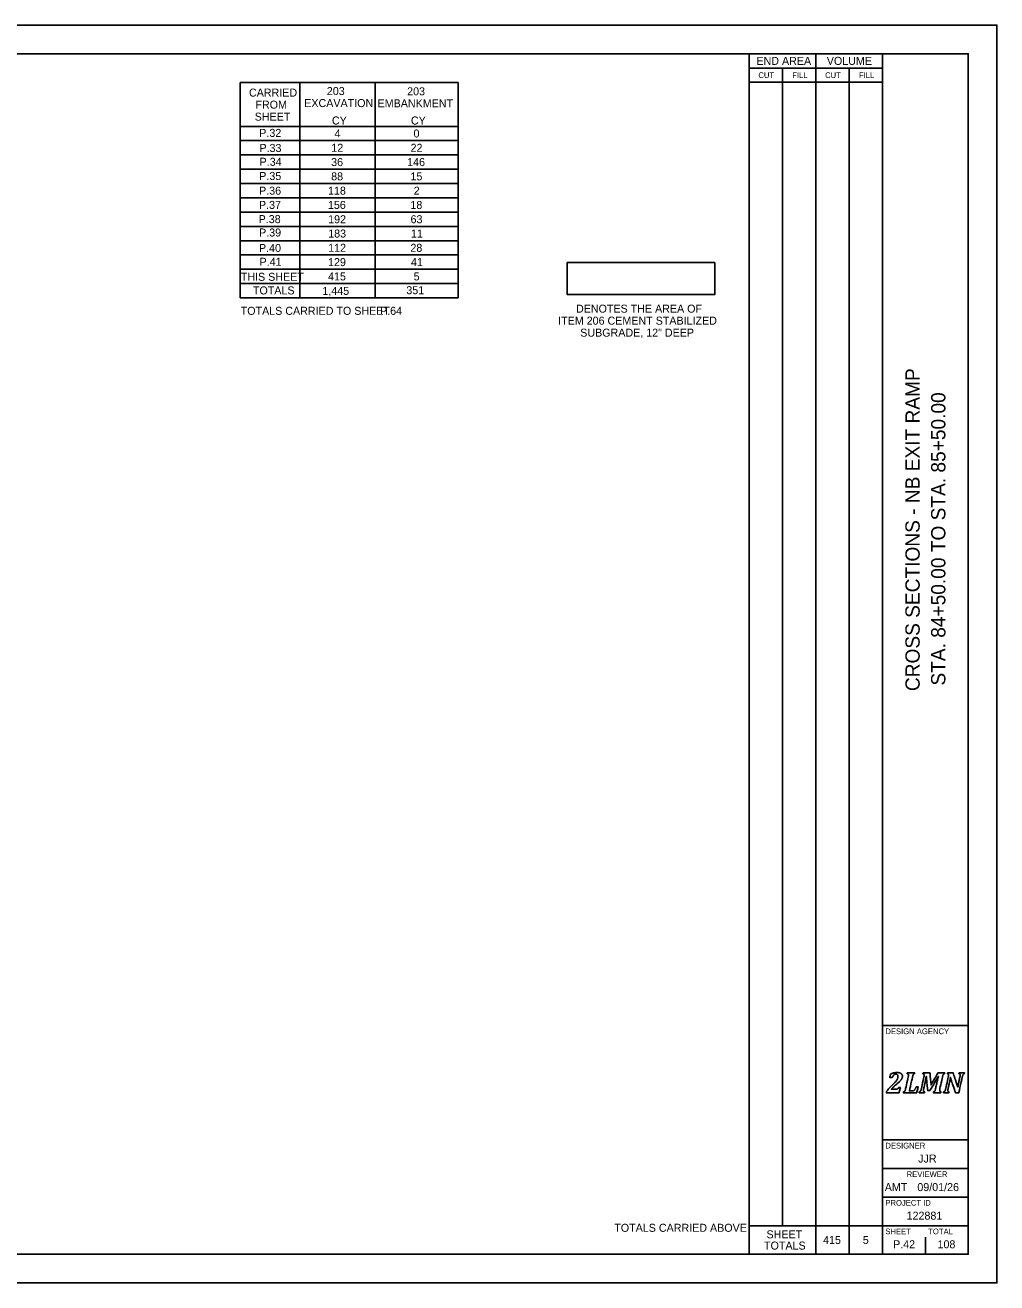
# Model space of a CAD drawing. Extents: x -32 to 34, y 0 to 22.
# Drawn here: x 17 to 34, y 0 to 22 of the extents above; entities that cross this region are included whole.
import ezdxf

# ---------------------------------------------------------------- set-up
doc = ezdxf.new("R2010")
doc.units = 0
for name, color, linetype in [('MD_P_Surface_Chemically_Stabilized_Subgrade', 7, 'Continuous'), ('SH_Border', 7, 'Continuous'), ('SH_Cut_Line', 7, 'Continuous'), ('SH_Data', 7, 'Continuous'), ('SH_Text', 7, 'Continuous')]:
    doc.layers.add(name, color=color, linetype=linetype)

msp = doc.modelspace()

# ---------------------------------------------------------------- linework, layer by layer
at = {"layer": 'MD_P_Surface_Chemically_Stabilized_Subgrade'}
for p, q in [((26.484, 17.846), (26.484, 17.287)), ((26.484, 17.846), (29.065, 17.846)), ((29.065, 17.287), (29.065, 17.846)), ((26.484, 17.287), (29.065, 17.287))]:
    msp.add_line(p, q, dxfattribs=at)
msp.add_lwpolyline([(29.065, 17.846), (29.065, 17.287), (26.484, 17.287), (26.484, 17.846)], close=True, dxfattribs=at)
at = {"layer": 'SH_Border'}
for p, q in [((32, 0.5), (32, 21.5)), ((32, 4.5), (33.5, 4.5)), ((32, 2.5), (33.5, 2.5)), ((32, 2), (33.5, 2)), ((32, 1.5), (33.5, 1.5)), ((32, 1), (33.5, 1))]:
    msp.add_line(p, q, dxfattribs=at)
msp.add_lwpolyline([(1.5, 21.5), (33.5, 21.5), (33.5, 0.5), (1.5, 0.5)], close=True, dxfattribs=at)
at = {"layer": 'SH_Cut_Line'}
msp.add_lwpolyline([(0, 0), (34, 0), (34, 22), (0, 22)], close=True, dxfattribs=at)
at = {"layer": 'SH_Data'}
for p, q in [((29.666, 0.5), (29.666, 21.5)), ((30.833, 0.5), (30.833, 21.5)), ((29.666, 21.25), (32, 21.25)), ((30.25, 1), (30.25, 21.25)), ((31.417, 0.5), (31.417, 21.25)), ((29.666, 21), (32, 21)), ((32.75, 3.5), (32.75, 3.5)), ((29.666, 1), (32, 1)), ((29.958, 0.75), (29.958, 0.75)), ((30.542, 0.75), (30.542, 0.75)), ((31.125, 0.75), (31.125, 0.75)), ((31.708, 0.75), (31.708, 0.75)), ((32.375, 0.675), (32.375, 0.675)), ((32.75, 0.5), (32.75, 0.8))]:
    msp.add_line(p, q, dxfattribs=at)
for points in [[(32.237, 3.388), (32.246, 3.388), (32.253, 3.389), (32.258, 3.39), (32.263, 3.392), (32.267, 3.394), (32.27, 3.397), (32.273, 3.401), (32.277, 3.408), (32.281, 3.417), (32.281, 3.417), (32.312, 3.417), (32.312, 3.417), (32.312, 3.417), (32.29, 3.326), (32.29, 3.326), (32.29, 3.326), (32.066, 3.326), (32.066, 3.326), (32.066, 3.326), (32.069, 3.343), (32.069, 3.343), (32.078, 3.358), (32.091, 3.375), (32.106, 3.394), (32.122, 3.412), (32.144, 3.435), (32.172, 3.462), (32.197, 3.486), (32.217, 3.506), (32.23, 3.521), (32.243, 3.537), (32.253, 3.551), (32.259, 3.566), (32.266, 3.58), (32.269, 3.595), (32.269, 3.61), (32.269, 3.622), (32.266, 3.632), (32.26, 3.64), (32.253, 3.647), (32.245, 3.65), (32.234, 3.65), (32.22, 3.65), (32.208, 3.646), (32.198, 3.636), (32.188, 3.627), (32.18, 3.613), (32.172, 3.593), (32.172, 3.593), (32.126, 3.593), (32.126, 3.593), (32.126, 3.593), (32.14, 3.654), (32.14, 3.654), (32.166, 3.663), (32.188, 3.669), (32.205, 3.673), (32.223, 3.676), (32.24, 3.678), (32.258, 3.678), (32.278, 3.678), (32.295, 3.675), (32.309, 3.669), (32.322, 3.664), (32.332, 3.656), (32.339, 3.646), (32.345, 3.637), (32.348, 3.626), (32.348, 3.613), (32.348, 3.602), (32.346, 3.591), (32.342, 3.581), (32.339, 3.571), (32.333, 3.56), (32.324, 3.549), (32.315, 3.539), (32.304, 3.526), (32.289, 3.513), (32.275, 3.499), (32.254, 3.482), (32.228, 3.46), (32.216, 3.45), (32.202, 3.438), (32.188, 3.425), (32.174, 3.412), (32.162, 3.4), (32.154, 3.391), (32.154, 3.391), (32.153, 3.388), (32.153, 3.388), (32.153, 3.388), (32.237, 3.388), (32.237, 3.388)], [(32.237, 3.388), (32.237, 3.388), (32.153, 3.388), (32.153, 3.388), (32.153, 3.388), (32.154, 3.391), (32.154, 3.391), (32.162, 3.4), (32.174, 3.412), (32.188, 3.425), (32.202, 3.438), (32.216, 3.45), (32.228, 3.46), (32.254, 3.482), (32.275, 3.499), (32.289, 3.513), (32.304, 3.526), (32.315, 3.539), (32.324, 3.549), (32.333, 3.56), (32.339, 3.571), (32.342, 3.581), (32.346, 3.591), (32.348, 3.602), (32.348, 3.613), (32.348, 3.626), (32.345, 3.637), (32.339, 3.646), (32.332, 3.656), (32.322, 3.664), (32.309, 3.669), (32.295, 3.675), (32.278, 3.678), (32.258, 3.678), (32.24, 3.678), (32.223, 3.676), (32.205, 3.673), (32.188, 3.669), (32.166, 3.663), (32.14, 3.654), (32.14, 3.654), (32.126, 3.593), (32.126, 3.593), (32.126, 3.593), (32.172, 3.593), (32.172, 3.593), (32.18, 3.613), (32.188, 3.627), (32.198, 3.636), (32.208, 3.646), (32.22, 3.65), (32.234, 3.65), (32.245, 3.65), (32.253, 3.647), (32.26, 3.64), (32.266, 3.632), (32.269, 3.622), (32.269, 3.61), (32.269, 3.595), (32.266, 3.58), (32.259, 3.566), (32.253, 3.551), (32.243, 3.537), (32.23, 3.521), (32.217, 3.506), (32.197, 3.486), (32.172, 3.462), (32.144, 3.435), (32.122, 3.412), (32.106, 3.394), (32.091, 3.375), (32.078, 3.358), (32.069, 3.343), (32.069, 3.343), (32.066, 3.326), (32.066, 3.326), (32.066, 3.326), (32.29, 3.326), (32.29, 3.326), (32.29, 3.326), (32.312, 3.417), (32.312, 3.417), (32.312, 3.417), (32.281, 3.417), (32.281, 3.417), (32.277, 3.408), (32.273, 3.401), (32.27, 3.397), (32.267, 3.394), (32.263, 3.392), (32.258, 3.39), (32.253, 3.389), (32.246, 3.388), (32.237, 3.388)], [(32.518, 3.356), (32.527, 3.356), (32.533, 3.357), (32.538, 3.358), (32.542, 3.36), (32.546, 3.362), (32.55, 3.365), (32.554, 3.368), (32.558, 3.372), (32.562, 3.377), (32.567, 3.382), (32.571, 3.388), (32.576, 3.397), (32.58, 3.405), (32.585, 3.415), (32.589, 3.427), (32.589, 3.427), (32.624, 3.427), (32.624, 3.427), (32.624, 3.427), (32.598, 3.326), (32.598, 3.326), (32.598, 3.326), (32.365, 3.326), (32.365, 3.326), (32.365, 3.326), (32.369, 3.343), (32.369, 3.343), (32.376, 3.345), (32.381, 3.348), (32.385, 3.351), (32.389, 3.355), (32.392, 3.36), (32.395, 3.366), (32.398, 3.373), (32.4, 3.382), (32.403, 3.395), (32.403, 3.395), (32.449, 3.605), (32.449, 3.605), (32.452, 3.615), (32.453, 3.625), (32.453, 3.635), (32.453, 3.642), (32.451, 3.647), (32.448, 3.651), (32.444, 3.654), (32.439, 3.656), (32.432, 3.657), (32.432, 3.657), (32.435, 3.674), (32.435, 3.674), (32.435, 3.674), (32.563, 3.674), (32.563, 3.674), (32.563, 3.674), (32.559, 3.657), (32.559, 3.657), (32.552, 3.655), (32.547, 3.652), (32.543, 3.649), (32.539, 3.645), (32.536, 3.64), (32.533, 3.634), (32.531, 3.627), (32.528, 3.618), (32.525, 3.605), (32.525, 3.605), (32.47, 3.356), (32.47, 3.356), (32.47, 3.356), (32.518, 3.356), (32.518, 3.356)], [(32.518, 3.356), (32.518, 3.356), (32.47, 3.356), (32.47, 3.356), (32.47, 3.356), (32.525, 3.605), (32.525, 3.605), (32.528, 3.618), (32.531, 3.627), (32.533, 3.634), (32.536, 3.64), (32.539, 3.645), (32.543, 3.649), (32.547, 3.652), (32.552, 3.655), (32.559, 3.657), (32.559, 3.657), (32.563, 3.674), (32.563, 3.674), (32.563, 3.674), (32.435, 3.674), (32.435, 3.674), (32.435, 3.674), (32.432, 3.657), (32.432, 3.657), (32.439, 3.656), (32.444, 3.654), (32.448, 3.651), (32.451, 3.647), (32.453, 3.642), (32.453, 3.635), (32.453, 3.625), (32.452, 3.615), (32.449, 3.605), (32.449, 3.605), (32.403, 3.395), (32.403, 3.395), (32.4, 3.382), (32.398, 3.373), (32.395, 3.366), (32.392, 3.36), (32.389, 3.355), (32.385, 3.351), (32.381, 3.348), (32.376, 3.345), (32.369, 3.343), (32.369, 3.343), (32.365, 3.326), (32.365, 3.326), (32.365, 3.326), (32.598, 3.326), (32.598, 3.326), (32.598, 3.326), (32.624, 3.427), (32.624, 3.427), (32.624, 3.427), (32.589, 3.427), (32.589, 3.427), (32.585, 3.415), (32.58, 3.405), (32.576, 3.397), (32.571, 3.388), (32.567, 3.382), (32.562, 3.377), (32.558, 3.372), (32.554, 3.368), (32.55, 3.365), (32.546, 3.362), (32.542, 3.36), (32.538, 3.358), (32.533, 3.357), (32.527, 3.356), (32.518, 3.356)], [(32.829, 3.674), (32.829, 3.674), (32.849, 3.461), (32.849, 3.461), (32.849, 3.461), (32.969, 3.674), (32.969, 3.674), (32.969, 3.674), (33.087, 3.674), (33.087, 3.674), (33.087, 3.674), (33.084, 3.657), (33.084, 3.657), (33.077, 3.655), (33.071, 3.652), (33.067, 3.649), (33.064, 3.645), (33.06, 3.64), (33.058, 3.634), (33.055, 3.627), (33.052, 3.618), (33.05, 3.605), (33.05, 3.605), (33.003, 3.395), (33.003, 3.395), (33.002, 3.39), (33.002, 3.387), (33.001, 3.384), (33.001, 3.382), (33.001, 3.379), (33, 3.376), (33, 3.373), (33, 3.369), (33, 3.365), (33, 3.358), (33.002, 3.353), (33.005, 3.349), (33.008, 3.346), (33.014, 3.344), (33.021, 3.343), (33.021, 3.343), (33.018, 3.326), (33.018, 3.326), (33.018, 3.326), (32.89, 3.326), (32.89, 3.326), (32.89, 3.326), (32.893, 3.343), (32.893, 3.343), (32.9, 3.345), (32.906, 3.348), (32.91, 3.351), (32.914, 3.355), (32.917, 3.36), (32.919, 3.366), (32.922, 3.373), (32.925, 3.382), (32.928, 3.395), (32.928, 3.395), (32.951, 3.502), (32.951, 3.502), (32.954, 3.513), (32.957, 3.529), (32.962, 3.548), (32.967, 3.568), (32.972, 3.588), (32.978, 3.609), (32.978, 3.609), (32.973, 3.609), (32.973, 3.609), (32.965, 3.594), (32.957, 3.579), (32.948, 3.563), (32.948, 3.563), (32.833, 3.364), (32.833, 3.364), (32.833, 3.364), (32.792, 3.364), (32.792, 3.364), (32.792, 3.364), (32.775, 3.518), (32.775, 3.518), (32.773, 3.537), (32.772, 3.554), (32.77, 3.569), (32.769, 3.583), (32.768, 3.597), (32.768, 3.611), (32.768, 3.611), (32.764, 3.611), (32.764, 3.611), (32.761, 3.596), (32.758, 3.578), (32.755, 3.558), (32.751, 3.538), (32.747, 3.521), (32.744, 3.507), (32.744, 3.507), (32.72, 3.395), (32.72, 3.395), (32.719, 3.39), (32.718, 3.387), (32.718, 3.384), (32.717, 3.382), (32.717, 3.379), (32.717, 3.376), (32.717, 3.373), (32.716, 3.369), (32.716, 3.365), (32.716, 3.358), (32.718, 3.353), (32.721, 3.349), (32.725, 3.346), (32.73, 3.344), (32.738, 3.343), (32.738, 3.343), (32.734, 3.326), (32.734, 3.326), (32.734, 3.326), (32.641, 3.326), (32.641, 3.326), (32.641, 3.326), (32.644, 3.343), (32.644, 3.343), (32.651, 3.345), (32.657, 3.348), (32.661, 3.351), (32.665, 3.355), (32.668, 3.36), (32.67, 3.366), (32.673, 3.373), (32.676, 3.382), (32.679, 3.395), (32.679, 3.395), (32.725, 3.605), (32.725, 3.605), (32.727, 3.615), (32.728, 3.625), (32.728, 3.635), (32.728, 3.642), (32.727, 3.647), (32.723, 3.651), (32.72, 3.654), (32.715, 3.656), (32.707, 3.657), (32.707, 3.657), (32.711, 3.674), (32.711, 3.674), (32.711, 3.674), (32.829, 3.674), (32.829, 3.674)], [(32.829, 3.674), (32.829, 3.674), (32.711, 3.674), (32.711, 3.674), (32.711, 3.674), (32.707, 3.657), (32.707, 3.657), (32.715, 3.656), (32.72, 3.654), (32.723, 3.651), (32.727, 3.647), (32.728, 3.642), (32.728, 3.635), (32.728, 3.625), (32.727, 3.615), (32.725, 3.605), (32.725, 3.605), (32.679, 3.395), (32.679, 3.395), (32.676, 3.382), (32.673, 3.373), (32.67, 3.366), (32.668, 3.36), (32.665, 3.355), (32.661, 3.351), (32.657, 3.348), (32.651, 3.345), (32.644, 3.343), (32.644, 3.343), (32.641, 3.326), (32.641, 3.326), (32.641, 3.326), (32.734, 3.326), (32.734, 3.326), (32.734, 3.326), (32.738, 3.343), (32.738, 3.343), (32.73, 3.344), (32.725, 3.346), (32.721, 3.349), (32.718, 3.353), (32.716, 3.358), (32.716, 3.365), (32.716, 3.369), (32.717, 3.373), (32.717, 3.376), (32.717, 3.379), (32.717, 3.382), (32.718, 3.384), (32.718, 3.387), (32.719, 3.39), (32.72, 3.395), (32.72, 3.395), (32.744, 3.507), (32.744, 3.507), (32.747, 3.521), (32.751, 3.538), (32.755, 3.558), (32.758, 3.578), (32.761, 3.596), (32.764, 3.611), (32.764, 3.611), (32.768, 3.611), (32.768, 3.611), (32.768, 3.597), (32.769, 3.583), (32.77, 3.569), (32.772, 3.554), (32.773, 3.537), (32.775, 3.518), (32.775, 3.518), (32.792, 3.364), (32.792, 3.364), (32.792, 3.364), (32.833, 3.364), (32.833, 3.364), (32.833, 3.364), (32.948, 3.563), (32.948, 3.563), (32.957, 3.579), (32.965, 3.594), (32.973, 3.609), (32.973, 3.609), (32.978, 3.609), (32.978, 3.609), (32.972, 3.588), (32.967, 3.568), (32.962, 3.548), (32.957, 3.529), (32.954, 3.513), (32.951, 3.502), (32.951, 3.502), (32.928, 3.395), (32.928, 3.395), (32.925, 3.382), (32.922, 3.373), (32.919, 3.366), (32.917, 3.36), (32.914, 3.355), (32.91, 3.351), (32.906, 3.348), (32.9, 3.345), (32.893, 3.343), (32.893, 3.343), (32.89, 3.326), (32.89, 3.326), (32.89, 3.326), (33.018, 3.326), (33.018, 3.326), (33.018, 3.326), (33.021, 3.343), (33.021, 3.343), (33.014, 3.344), (33.008, 3.346), (33.005, 3.349), (33.002, 3.353), (33, 3.358), (33, 3.365), (33, 3.369), (33, 3.373), (33, 3.376), (33.001, 3.379), (33.001, 3.382), (33.001, 3.384), (33.002, 3.387), (33.002, 3.39), (33.003, 3.395), (33.003, 3.395), (33.05, 3.605), (33.05, 3.605), (33.052, 3.618), (33.055, 3.627), (33.058, 3.634), (33.06, 3.64), (33.064, 3.645), (33.067, 3.649), (33.071, 3.652), (33.077, 3.655), (33.084, 3.657), (33.084, 3.657), (33.087, 3.674), (33.087, 3.674), (33.087, 3.674), (32.969, 3.674), (32.969, 3.674), (32.969, 3.674), (32.849, 3.461), (32.849, 3.461), (32.849, 3.461), (32.829, 3.674), (32.829, 3.674)], [(33.137, 3.674), (33.137, 3.674), (33.234, 3.674), (33.234, 3.674), (33.234, 3.674), (33.283, 3.53), (33.283, 3.53), (33.296, 3.49), (33.307, 3.456), (33.315, 3.426), (33.315, 3.426), (33.318, 3.426), (33.318, 3.426), (33.323, 3.455), (33.329, 3.488), (33.337, 3.523), (33.337, 3.523), (33.355, 3.605), (33.355, 3.605), (33.357, 3.615), (33.358, 3.625), (33.358, 3.635), (33.358, 3.642), (33.357, 3.647), (33.353, 3.651), (33.35, 3.654), (33.345, 3.656), (33.337, 3.657), (33.337, 3.657), (33.341, 3.674), (33.341, 3.674), (33.341, 3.674), (33.434, 3.674), (33.434, 3.674), (33.434, 3.674), (33.431, 3.657), (33.431, 3.657), (33.424, 3.655), (33.418, 3.652), (33.414, 3.649), (33.41, 3.645), (33.407, 3.64), (33.405, 3.634), (33.402, 3.627), (33.399, 3.618), (33.396, 3.605), (33.396, 3.605), (33.335, 3.326), (33.335, 3.326), (33.335, 3.326), (33.277, 3.326), (33.277, 3.326), (33.277, 3.326), (33.216, 3.504), (33.216, 3.504), (33.211, 3.518), (33.207, 3.531), (33.204, 3.543), (33.2, 3.556), (33.195, 3.571), (33.19, 3.59), (33.19, 3.59), (33.186, 3.59), (33.186, 3.59), (33.185, 3.579), (33.182, 3.563), (33.179, 3.543), (33.175, 3.523), (33.17, 3.501), (33.165, 3.478), (33.165, 3.478), (33.147, 3.395), (33.147, 3.395), (33.146, 3.39), (33.145, 3.387), (33.145, 3.384), (33.144, 3.382), (33.144, 3.379), (33.144, 3.376), (33.143, 3.373), (33.143, 3.369), (33.143, 3.365), (33.143, 3.358), (33.145, 3.353), (33.148, 3.349), (33.152, 3.346), (33.157, 3.344), (33.164, 3.343), (33.164, 3.343), (33.161, 3.326), (33.161, 3.326), (33.161, 3.326), (33.067, 3.326), (33.067, 3.326), (33.067, 3.326), (33.071, 3.343), (33.071, 3.343), (33.078, 3.345), (33.083, 3.348), (33.087, 3.351), (33.091, 3.355), (33.094, 3.36), (33.097, 3.366), (33.1, 3.373), (33.102, 3.382), (33.105, 3.395), (33.105, 3.395), (33.151, 3.605), (33.151, 3.605), (33.154, 3.615), (33.155, 3.625), (33.155, 3.635), (33.155, 3.642), (33.153, 3.647), (33.15, 3.651), (33.146, 3.654), (33.141, 3.656), (33.134, 3.657), (33.134, 3.657), (33.137, 3.674), (33.137, 3.674)], [(33.137, 3.674), (33.137, 3.674), (33.134, 3.657), (33.134, 3.657), (33.141, 3.656), (33.146, 3.654), (33.15, 3.651), (33.153, 3.647), (33.155, 3.642), (33.155, 3.635), (33.155, 3.625), (33.154, 3.615), (33.151, 3.605), (33.151, 3.605), (33.105, 3.395), (33.105, 3.395), (33.102, 3.382), (33.1, 3.373), (33.097, 3.366), (33.094, 3.36), (33.091, 3.355), (33.087, 3.351), (33.083, 3.348), (33.078, 3.345), (33.071, 3.343), (33.071, 3.343), (33.067, 3.326), (33.067, 3.326), (33.067, 3.326), (33.161, 3.326), (33.161, 3.326), (33.161, 3.326), (33.164, 3.343), (33.164, 3.343), (33.157, 3.344), (33.152, 3.346), (33.148, 3.349), (33.145, 3.353), (33.143, 3.358), (33.143, 3.365), (33.143, 3.369), (33.143, 3.373), (33.144, 3.376), (33.144, 3.379), (33.144, 3.382), (33.145, 3.384), (33.145, 3.387), (33.146, 3.39), (33.147, 3.395), (33.147, 3.395), (33.165, 3.478), (33.165, 3.478), (33.17, 3.501), (33.175, 3.523), (33.179, 3.543), (33.182, 3.563), (33.185, 3.579), (33.186, 3.59), (33.186, 3.59), (33.19, 3.59), (33.19, 3.59), (33.195, 3.571), (33.2, 3.556), (33.204, 3.543), (33.207, 3.531), (33.211, 3.518), (33.216, 3.504), (33.216, 3.504), (33.277, 3.326), (33.277, 3.326), (33.277, 3.326), (33.335, 3.326), (33.335, 3.326), (33.335, 3.326), (33.396, 3.605), (33.396, 3.605), (33.399, 3.618), (33.402, 3.627), (33.405, 3.634), (33.407, 3.64), (33.41, 3.645), (33.414, 3.649), (33.418, 3.652), (33.424, 3.655), (33.431, 3.657), (33.431, 3.657), (33.434, 3.674), (33.434, 3.674), (33.434, 3.674), (33.341, 3.674), (33.341, 3.674), (33.341, 3.674), (33.337, 3.657), (33.337, 3.657), (33.345, 3.656), (33.35, 3.654), (33.353, 3.651), (33.357, 3.647), (33.358, 3.642), (33.358, 3.635), (33.358, 3.625), (33.357, 3.615), (33.355, 3.605), (33.355, 3.605), (33.337, 3.523), (33.337, 3.523), (33.329, 3.488), (33.323, 3.455), (33.318, 3.426), (33.318, 3.426), (33.315, 3.426), (33.315, 3.426), (33.307, 3.456), (33.296, 3.49), (33.283, 3.53), (33.283, 3.53), (33.234, 3.674), (33.234, 3.674), (33.234, 3.674), (33.137, 3.674), (33.137, 3.674)]]:
    msp.add_open_spline(points, degree=3, dxfattribs=at)
at = {"layer": 'SH_Text'}
for p, q in [((20.762, 20.994), (24.578, 20.994)), ((20.762, 20.994), (20.762, 17.23)), ((21.807, 20.994), (21.807, 17.23)), ((23.124, 20.994), (23.124, 17.23)), ((24.578, 20.994), (24.578, 17.23)), ((20.762, 20.23), (24.578, 20.23)), ((20.762, 19.98), (24.578, 19.98)), ((20.762, 19.73), (24.578, 19.73)), ((20.762, 19.48), (24.578, 19.48)), ((20.762, 19.23), (24.578, 19.23)), ((20.762, 18.98), (24.578, 18.98)), ((20.762, 18.73), (24.578, 18.73)), ((20.762, 18.48), (24.578, 18.48)), ((20.762, 18.23), (24.578, 18.23)), ((20.762, 17.98), (24.578, 17.98)), ((20.762, 17.73), (24.578, 17.73)), ((20.762, 17.48), (24.578, 17.48)), ((20.762, 17.23), (24.578, 17.23))]:
    msp.add_line(p, q, dxfattribs=at)

# ---------------------------------------------------------------- texts
at = {"layer": 'SH_Data'}
for s, height, p in [('END AREA', 0.14, (29.794, 21.305)), ('VOLUME', 0.14, (31.025, 21.305)), ('CUT', 0.1, (29.828, 21.075)), ('FILL', 0.1, (30.42, 21.075)), ('CUT', 0.1, (30.995, 21.075)), ('FILL', 0.1, (31.587, 21.075)), ('DESIGN AGENCY', 0.1, (32.05, 4.35)), ('DESIGNER', 0.1, (32.05, 2.35)), ('JJR', 0.14, (32.624, 2.105)), ('REVIEWER', 0.1, (32.422, 1.85)), ('AMT', 0.14, (32.039, 1.605)), ('09/01/26', 0.14, (32.609, 1.605)), ('PROJECT ID', 0.1, (32.05, 1.35)), ('122881', 0.14, (32.421, 1.105)), ('SHEET', 0.14, (29.97, 0.778)), ('SHEET', 0.1, (32.05, 0.85)), ('TOTAL', 0.1, (32.8, 0.85)), ('TOTALS', 0.14, (29.927, 0.582)), ('P.42', 0.14, (32.185, 0.605)), ('108', 0.14, (32.962, 0.605))]:
    msp.add_text(s, height=height, dxfattribs=at).set_placement(p)
for s, p in [('CROSS SECTIONS - NB EXIT RAMP', (32.65, 10.351)), ('STA. 84+50.00 TO STA. 85+50.00', (33.1, 10.448))]:
    msp.add_text(s, height=0.25, rotation=90, dxfattribs=at).set_placement(p)
at = {"layer": 'SH_Text'}
for s, p in [('203 ', (22.278, 20.777)), ('203', (23.683, 20.773)), ('CARRIED', (20.916, 20.75)), ('FROM', (21.029, 20.54)), ('EXCAVATION', (21.883, 20.567)), ('EMBANKMENT', (23.166, 20.563)), ('SHEET', (21.016, 20.33)), ('CY', (22.367, 20.262)), ('CY', (23.749, 20.262)), ('P.32', (21.096, 20.045)), ('4', (22.413, 20.035)), ('0', (23.795, 20.035)), ('P.33', (21.099, 19.782)), ('12', (22.357, 19.785)), ('22', (23.743, 19.785)), ('P.34', (21.102, 19.54)), ('36', (22.353, 19.535)), ('146', (23.683, 19.535)), ('P.35', (21.096, 19.291)), ('88', (22.354, 19.285)), ('15', (23.741, 19.285)), ('P.36', (21.093, 19.035)), ('118', (22.299, 19.035)), ('2', (23.798, 19.035)), ('P.37', (21.091, 18.786)), ('156', (22.297, 18.785)), ('18', (23.74, 18.785)), ('P.38', (21.085, 18.537)), ('192', (22.301, 18.535)), ('63', (23.743, 18.535)), ('P.39', (21.093, 18.303)), ('183', (22.302, 18.285)), ('11', (23.749, 18.285)), ('P.40', (21.091, 18.032)), ('112', (22.301, 18.035)), ('28', (23.74, 18.035)), ('P.41', (21.101, 17.79)), ('129', (22.299, 17.785)), ('41', (23.749, 17.785)), ('THIS SHEET', (20.773, 17.528)), ('415', (22.3, 17.535)), ('5', (23.797, 17.535)), ('TOTALS', (20.985, 17.29)), ('1,445', (22.2, 17.282)), ('351', (23.669, 17.294)), ('TOTALS CARRIED TO SHEET ', (20.771, 16.933)), ('P.64', (23.209, 16.933)), ('DENOTES THE AREA OF', (26.637, 16.971)), ('ITEM 206 CEMENT STABILIZED ', (26.325, 16.761)), ('SUBGRADE, 12" DEEP', (26.711, 16.551)), ('TOTALS CARRIED ABOVE', (27.307, 0.893)), ('415', (30.96, 0.68)), ('5', (31.655, 0.68))]:
    msp.add_text(s, height=0.14, dxfattribs=at).set_placement(p)

doc.saveas('drawing.dxf')
